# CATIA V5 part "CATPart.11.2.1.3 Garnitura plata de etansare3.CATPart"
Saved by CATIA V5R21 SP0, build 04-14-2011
Part number: Garnitura plata de etanşare.1.1
Bounding box of the stored display mesh (mm): x -4.5 to 4.5, y -4.5 to 4.5, z 0 to 2
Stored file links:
  C:\Users\MIRCEA\Desktop\MOM\Mogan\model\CATPart.11.2.1.3 Garnitura plata de etansare3.CATPart
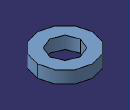
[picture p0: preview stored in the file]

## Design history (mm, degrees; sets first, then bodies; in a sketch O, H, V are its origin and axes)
Parameters
  Di = 5 mm
  De = 9 mm
  h = 2 mm
AxisSystem1: origin (0, 0, 0), X (1, 0, 0), Y (0, 1, 0), Z (0, 0, 1)
Body1 (main body)
  Sketch1 on xy-plane, origin (0, 0, 0), H (1, 0, 0), V (0, 1, 0)
    circle A1 centre (0, 0) radius 2.5
    circle A2 centre (0, 0) radius 4.5
    radius A1 = 2.5 {= Di/2}
    radius A2 = 4.5 {= De/2}
  Pad1: profile Sketch1, direction (0, 0, 1), length 2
